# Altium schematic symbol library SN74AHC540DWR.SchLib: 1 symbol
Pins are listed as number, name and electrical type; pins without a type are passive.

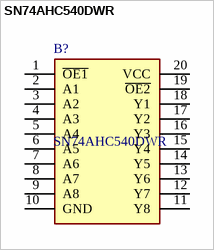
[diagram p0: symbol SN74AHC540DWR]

## SN74AHC540DWR
designator B?
Octal Buffers/Drivers With 3-State Outputs; Manufacturer_Name: Texas Instruments; Geometry.Height: 2.65mm
footprint SOIC127P1030X265-20N
pins: 1 ~{OE1}, 2 A1, 3 A2, 4 A3, 5 A4, 6 A5, 7 A6, 8 A7, 9 A8, 10 GND, 11 Y8, 12 Y7, 13 Y6, 14 Y5, 15 Y4, 16 Y3, 17 Y2, 18 Y1, 19 ~{OE2}, 20 VCC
